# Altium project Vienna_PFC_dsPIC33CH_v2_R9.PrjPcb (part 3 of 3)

## Sheet Vienna_PFC_EMIFilter.SchDoc
size D; DocumentNumber: 2; SheetNumber: 2; SheetTotal: 11
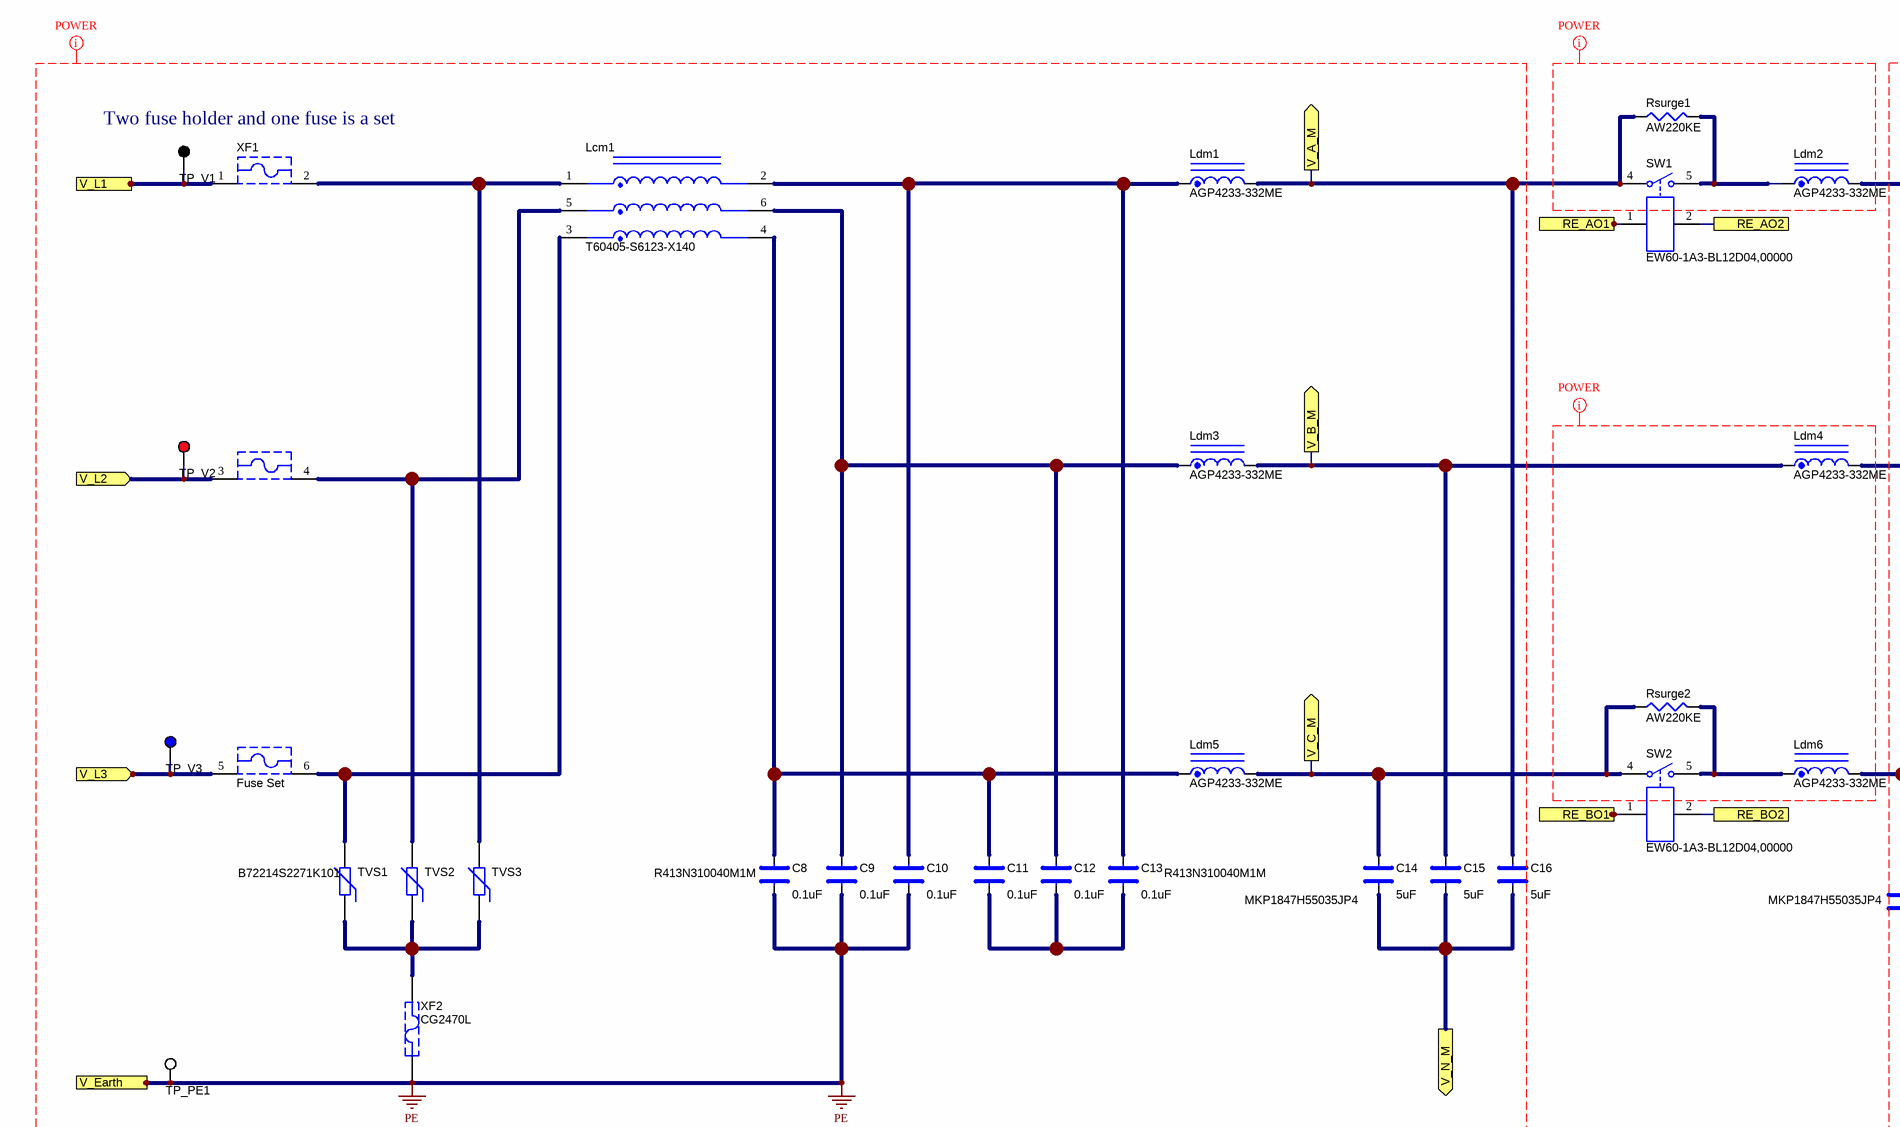
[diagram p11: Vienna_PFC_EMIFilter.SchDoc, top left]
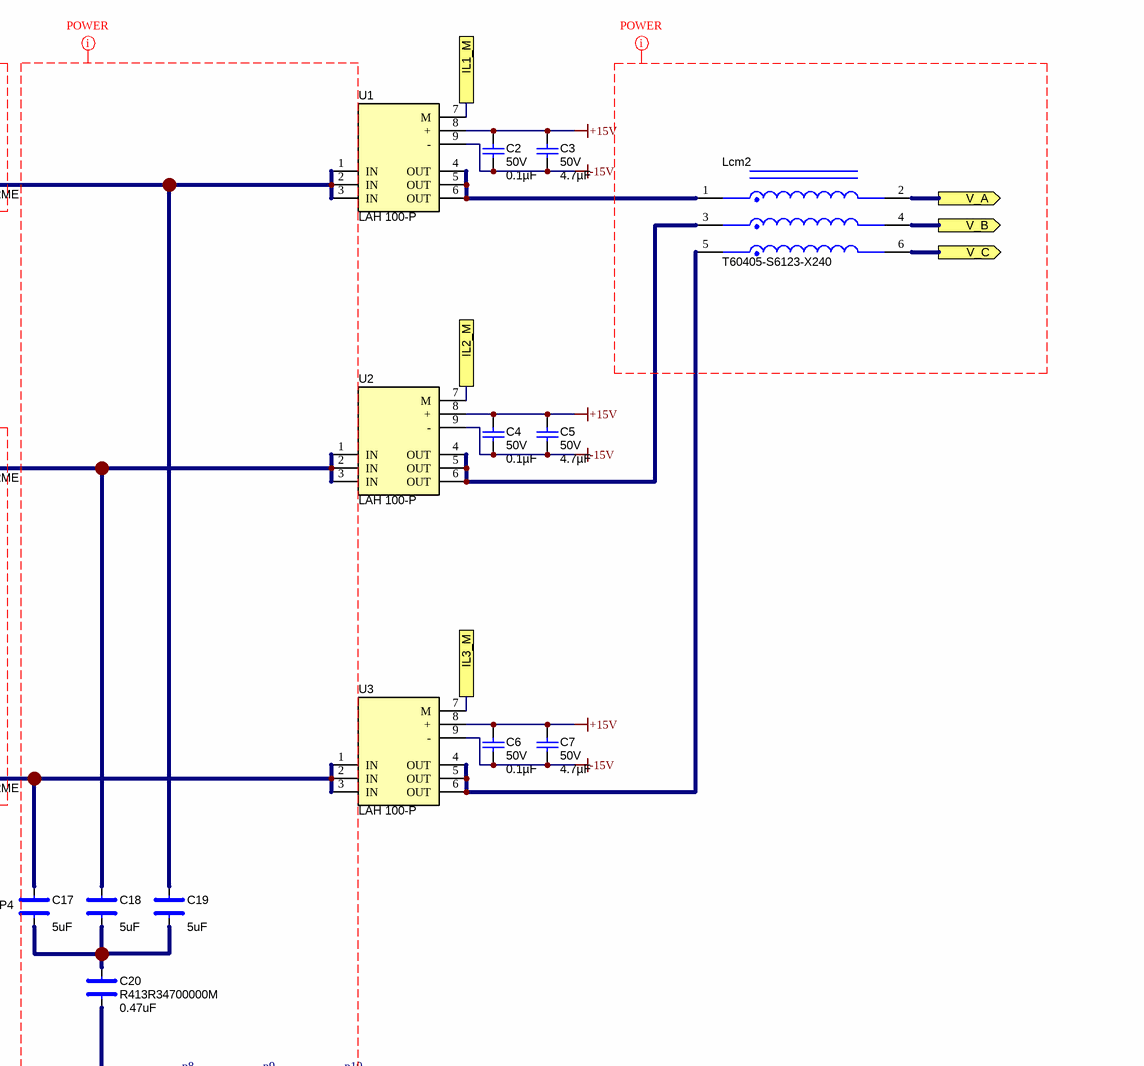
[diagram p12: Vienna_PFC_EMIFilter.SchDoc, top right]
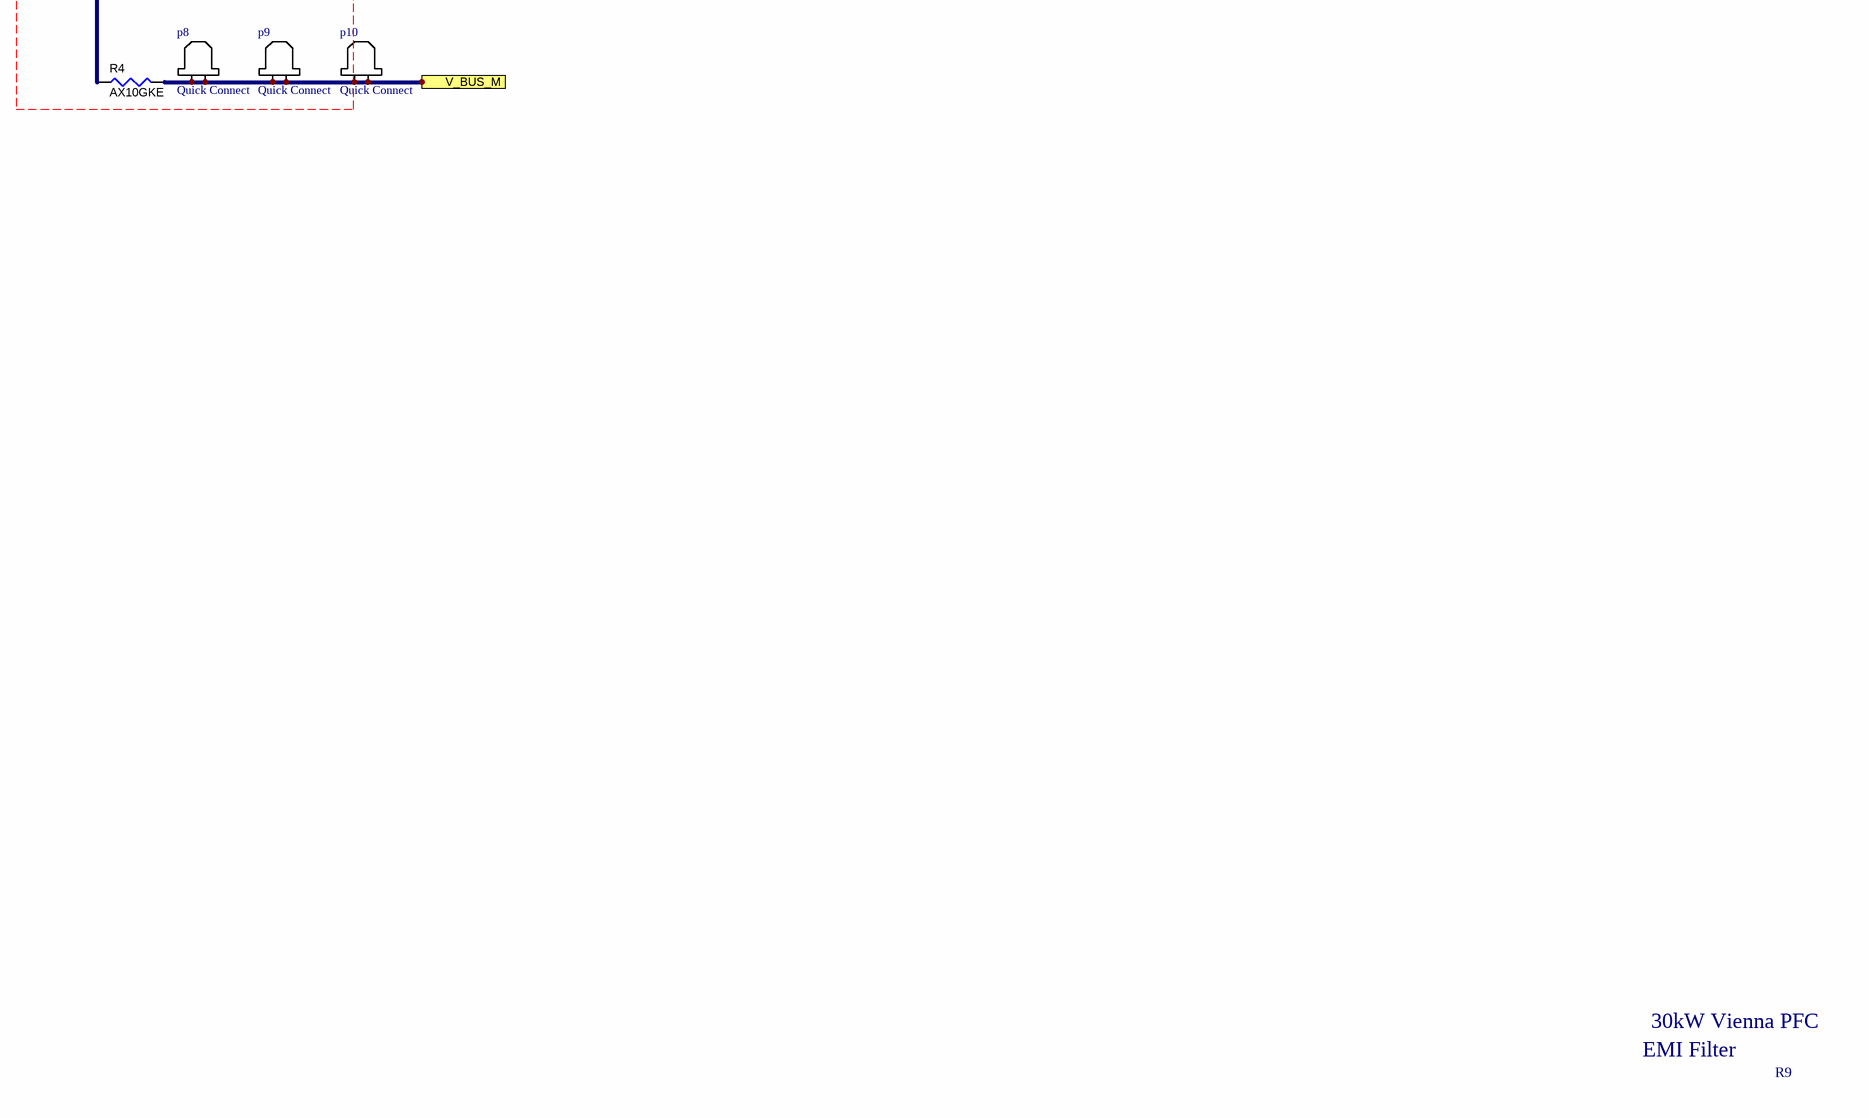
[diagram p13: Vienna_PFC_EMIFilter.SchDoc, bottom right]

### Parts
(Parts that share a designator on the sheet are numbered #1, #2 ... from top to bottom, then left to right.)
?#9  (no value)  (graphical)
C2  VDC_V: 50V  ValueDisplayed: 0.1µF  [0805_HV]  (hidden comment: C0805C104J5RACTU)
C3  VDC_V: 50V  ValueDisplayed: 4.7µF  [0805_HV]  (hidden comment: C2012X5R1H475K125AB)
C4  VDC_V: 50V  ValueDisplayed: 0.1µF  [0805_HV]  (hidden comment: C0805C104J5RACTU)
C5  VDC_V: 50V  ValueDisplayed: 4.7µF  [0805_HV]  (hidden comment: C2012X5R1H475K125AB)
C6  VDC_V: 50V  ValueDisplayed: 0.1µF  [0805_HV]  (hidden comment: C0805C104J5RACTU)
C7  VDC_V: 50V  ValueDisplayed: 4.7µF  [0805_HV]  (hidden comment: C2012X5R1H475K125AB)
C8  R413N310040M1M  value 0.1uF  [R413N310040M1M]
C9  value 0.1uF  [R413N310040M1M]  (hidden comment: R413N310040M1M)
C10  value 0.1uF  [R413N310040M1M]  (hidden comment: R413N310040M1M)
C11  value 0.1uF  [R413N310040M1M]  (hidden comment: R413N310040M1M)
C12  value 0.1uF  [R413N310040M1M]  (hidden comment: R413N310040M1M)
C13  R413N310040M1M  value 0.1uF  [R413N310040M1M]
C14  MKP1847H55035JP4  value 5uF  [MKP1847H55035JP4]
C15  value 5uF  [MKP1847H55035JP4]  (hidden comment: MKP1847H55035JP4)
C16  value 5uF  [MKP1847H55035JP4]  (hidden comment: MKP1847H55035JP4)
C17  MKP1847H55035JP4  value 5uF  [MKP1847H55035JP4]
C18  value 5uF  [MKP1847H55035JP4]  (hidden comment: MKP1847H55035JP4)
C19  value 5uF  [MKP1847H55035JP4]  (hidden comment: MKP1847H55035JP4)
C20  R413R34700000M  value 0.47uF  [R413R34700000M]
Lcm1  T60405-S6123-X140  [T60405-S6123-X140]
Lcm2  T60405-S6123-X240  [T60405-S6123-X240]
Ldm1  AGP4233-332ME  [AGP4233-332ME]
Ldm2  AGP4233-332ME  [AGP4233-332ME]
Ldm3  AGP4233-332ME  [AGP4233-332ME]
Ldm4  AGP4233-332ME  [AGP4233-332ME]
Ldm5  AGP4233-332ME  [AGP4233-332ME]
Ldm6  AGP4233-332ME  [AGP4233-332ME]
p8  Quick Connect  [Quick Connect-4.75mm]
p9  Quick Connect  [Quick Connect-4.75mm]
p10  Quick Connect  [Quick Connect-4.75mm]
R4  AX10GKE  [AX10GKE]
Rsurge1  AW220KE  [AW220KE]
Rsurge2  AW220KE  [AW220KE]
SW1  EW60-1A3-BL12D04,00000  [EW60-1A3-BL12D04,00000]
SW2  EW60-1A3-BL12D04,00000  [EW60-1A3-BL12D04,00000]
TP_PE1  5012  [Keystone5012]  (value not drawn)
TP_V1  5011  [Keystone5011]  (value not drawn)
TP_V2  5010  [Keystone5010]  (value not drawn)
TP_V3  5127  [Keystone5127]  (value not drawn)
TVS1  B72214S2271K101  [B72214S2271K101]
TVS2  B72214S2271K101  [B72214S2271K101]  (value not drawn)
TVS3  B72214S2271K101  [B72214S2271K101]  (value not drawn)
U1  LAH 100-P  [LAH 100-P]
U2  LAH 100-P  [LAH 100-P]
U3  LAH 100-P  [LAH 100-P]
XF1  Fuse Set  [FuseHolde_Set]
XF2  CG2470L  [CG2470L]

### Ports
IL1_M, IL2_M, IL3_M, RE_AO1, RE_AO2, RE_BO1, RE_BO2, V_A (out), V_A_M (out), V_B (out), V_B_M (out), V_BUS_M, V_C (out), V_C_M (out), V_Earth (in), V_L1 (in), V_L2 (in), V_L3 (in), V_N_M (out)

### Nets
+15V: C2.1 C3.1 C4.1 C5.1 C6.1 C7.1 U1.8(+) U2.8(+) U3.8(+)
-15V: C2.2 C3.2 C4.2 C5.2 C6.2 C7.2 U1.9(-) U2.9(-) U3.9(-)
PE: C8.1 C9.1 C10.1 TP_PE1.1 XF2.2 ; port V_Earth
V_BUS_M: p8.1 p9.1 p10.1 R4.2 ; port V_BUS_M
V_N_Meas: C14.1 C15.1 C16.1 ; port V_N_M
NetC8_2: C8.2 C11.2 Lcm1.4 Ldm5.1
NetC9_2: C9.2 C12.2 Lcm1.6 Ldm3.1
NetC10_2: C10.2 C13.2 Lcm1.2 Ldm1.1
NetC11_1: C11.1 C12.1 C13.1
NetC14_2: C14.2 Ldm5.2 Rsurge2.1 SW2.4 ; port V_C_M
NetC15_2: C15.2 Ldm3.2 Ldm4.1 ; port V_B_M
NetC16_2: C16.2 Ldm1.2 Rsurge1.1 SW1.4 ; port V_A_M
NetC17_1: C17.1 C18.1 C19.1 C20.2
NetC17_2: C17.2 Ldm6.2 U3.1(IN) U3.2(IN) U3.3(IN)
NetC18_2: C18.2 Ldm4.2 U2.1(IN) U2.2(IN) U2.3(IN)
NetC19_2: C19.2 Ldm2.2 U1.1(IN) U1.2(IN) U1.3(IN)
NetC20_1: C20.1 R4.1
NetLboost1_1: Lcm2.2 ; port V_A
NetLboost2_1: Lcm2.4 ; port V_B
NetLboost3_1: Lcm2.6 ; port V_C
NetLcm1_1: Lcm1.1 TVS3.2 XF1.2
NetLcm1_3: Lcm1.3 TVS1.2 XF1.6
NetLcm1_5: Lcm1.5 TVS2.2 XF1.4
NetLcm2_1: Lcm2.1 U1.4(OUT) U1.5(OUT) U1.6(OUT)
NetLcm2_3: Lcm2.3 U2.4(OUT) U2.5(OUT) U2.6(OUT)
NetLcm2_5: Lcm2.5 U3.4(OUT) U3.5(OUT) U3.6(OUT)
NetLdm2_1: Ldm2.1 Rsurge1.2 SW1.5
NetLdm6_1: Ldm6.1 Rsurge2.2 SW2.5
NetP1_1: TP_V1.1 XF1.1 ; port V_L1
NetP3_1: TP_V2.1 XF1.3 ; port V_L2
NetP5_1: TP_V3.1 XF1.5 ; port V_L3
NetR171_2: U1.7(M) ; port IL1_M
NetR174_2: U2.7(M) ; port IL2_M
NetR177_2: U3.7(M) ; port IL3_M
NetR180_2: SW1.1 ; port RE_AO1
NetR181_2: SW1.2 ; port RE_AO2
NetR182_2: SW2.1 ; port RE_BO1
NetR183_2: SW2.2 ; port RE_BO2
NetTVS1_1: TVS1.1 TVS2.1 TVS3.1 XF2.1

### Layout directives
net class POWER: (no net found under the mark), PE

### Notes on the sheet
- (near TP_V1) Two fuse holder and one fuse is a set
- 30kW Vienna PFC
- EMI Filter
- R9

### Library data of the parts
?#9 = Title Block D
C2 C4 C6 = C0805C104J5RACTU: CAP, CERM, 0.1 µF, 50 V, +/- 5%, X7R, 0805; Manufacturer: Kemet; CompType: Capacitor; Tolerance_%: 5; TaMin_C: -55; TaMax_C: 125; Cap_Case: 0805; AEC Category: Q200
C3 C5 C7 = C2012X5R1H475K125AB: CAP, CERM, 4.7 µF, 50 V, +/- 10%, X5R, 0805; Manufacturer: TDK; Polarized: N; CompType: Capacitor; Value: 4.7uF; U/M: EA; Cap_F: 0.0000047; Tolerance_%: 10; Value1: Unknown; TaMin_C: -55; TaMax_C: 85; Cap_Case: 0805; AEC Category: Q200
C8-C13 = R413N310040M1M: CAP FILM 0.1UF 20% 1KVDC RADIAL; Manufacturer: KEMET; CompType: Film Capacitors
C14-C19 = MKP1847H55035JP4: CAP FILM 5UF 5% 700VDC RAD 4LDS; Manufacturer: Vishay BC Components; CompType: Film Capacitors
C20 = R413R34700000M: CAP FILM 0.47UF 20% 1KVDC RADIAL; Manufacturer: KEMET; CompType: Film Capacitors
Lcm1 = T60405-S6123-X140: Common Mode Chokes / Filters 580 uH 40A horiz. 2.5mH; Manufacturer: Vacuumschmelze
Lcm2 = T60405-S6123-X240: Common Mode Chokes / Filters CM Choke 3 phase 40A horiz. 1.5mH; Manufacturer: Vacuumschmelze
Ldm1-Ldm6 = AGP4233-332ME: FIXED IND 3.3UH 34A  TH, Coilcraft; CompType: Fixed Inductors
p8-p10 = Quick Connect: 0.187" (4.75mm) Quick Connect Male Solder
R4 = AX10GKE: RES 1 OHM 3.5W 10% RADIAL; Manufacturer: Ohmite; CompType: Through Hole Resistors
Rsurge1 Rsurge2 = AW220KE: RES 22 OHM 2.5W 10% RADIAL; Manufacturer: Ohmite; CompType: Through Hole Resistors
SW1 SW2 = EW60-1A3-BL12D04: RELAY GEN PURPOSE SPST 60A 12V; Manufacturer: TE Connectivity Potter & Brumfield Relays; CompType: Power Relays
TP_PE1 = 5012: Test Point, Multipurpose, White, TH; Manufacturer: Keystone; CompType: Test Point Loop; ContactFinish: Silver
TP_V1 = 5011: Test Point, Multipurpose, Black, TH; Manufacturer: Keystone; CompType: Test Point Loop; ContactFinish: Silver
TP_V2 = 5010: Test Point, Multipurpose, Red, TH; Manufacturer: Keystone; CompType: Test Point Loop; ContactFinish: Silver
TP_V3 = 5127: Test Point, Multipurpose, Blue, TH; Manufacturer: Keystone; CompType: Test Point Loop; U/M: EA; ContactFinish: Silver
TVS1-TVS3 = B72214S2271K101: VARISTOR 430V 6KA DISC 14MM, EPCOS (TDK); CompType: TVS - Varistors, MOVs
U1-U3 = LAH 100-P: SENSOR CURRENT HALL 100A AC/DC; Manufacturer: LEM USA Inc.; CompType: Current Transducers
XF1 = Fuse Set: 6*5591-52-R, 3*50C14X51AM
XF2 = CG2470L: GDT 470V 20KA THROUGH HOLE,  Littelfuse Inc.; CompType: Gas Discharge Tube Arresters (GDT)

## Sheet Vienna_PFC_Relay.SchDoc
size C; DocumentNumber: 9; SheetNumber: 9; SheetTotal: 11
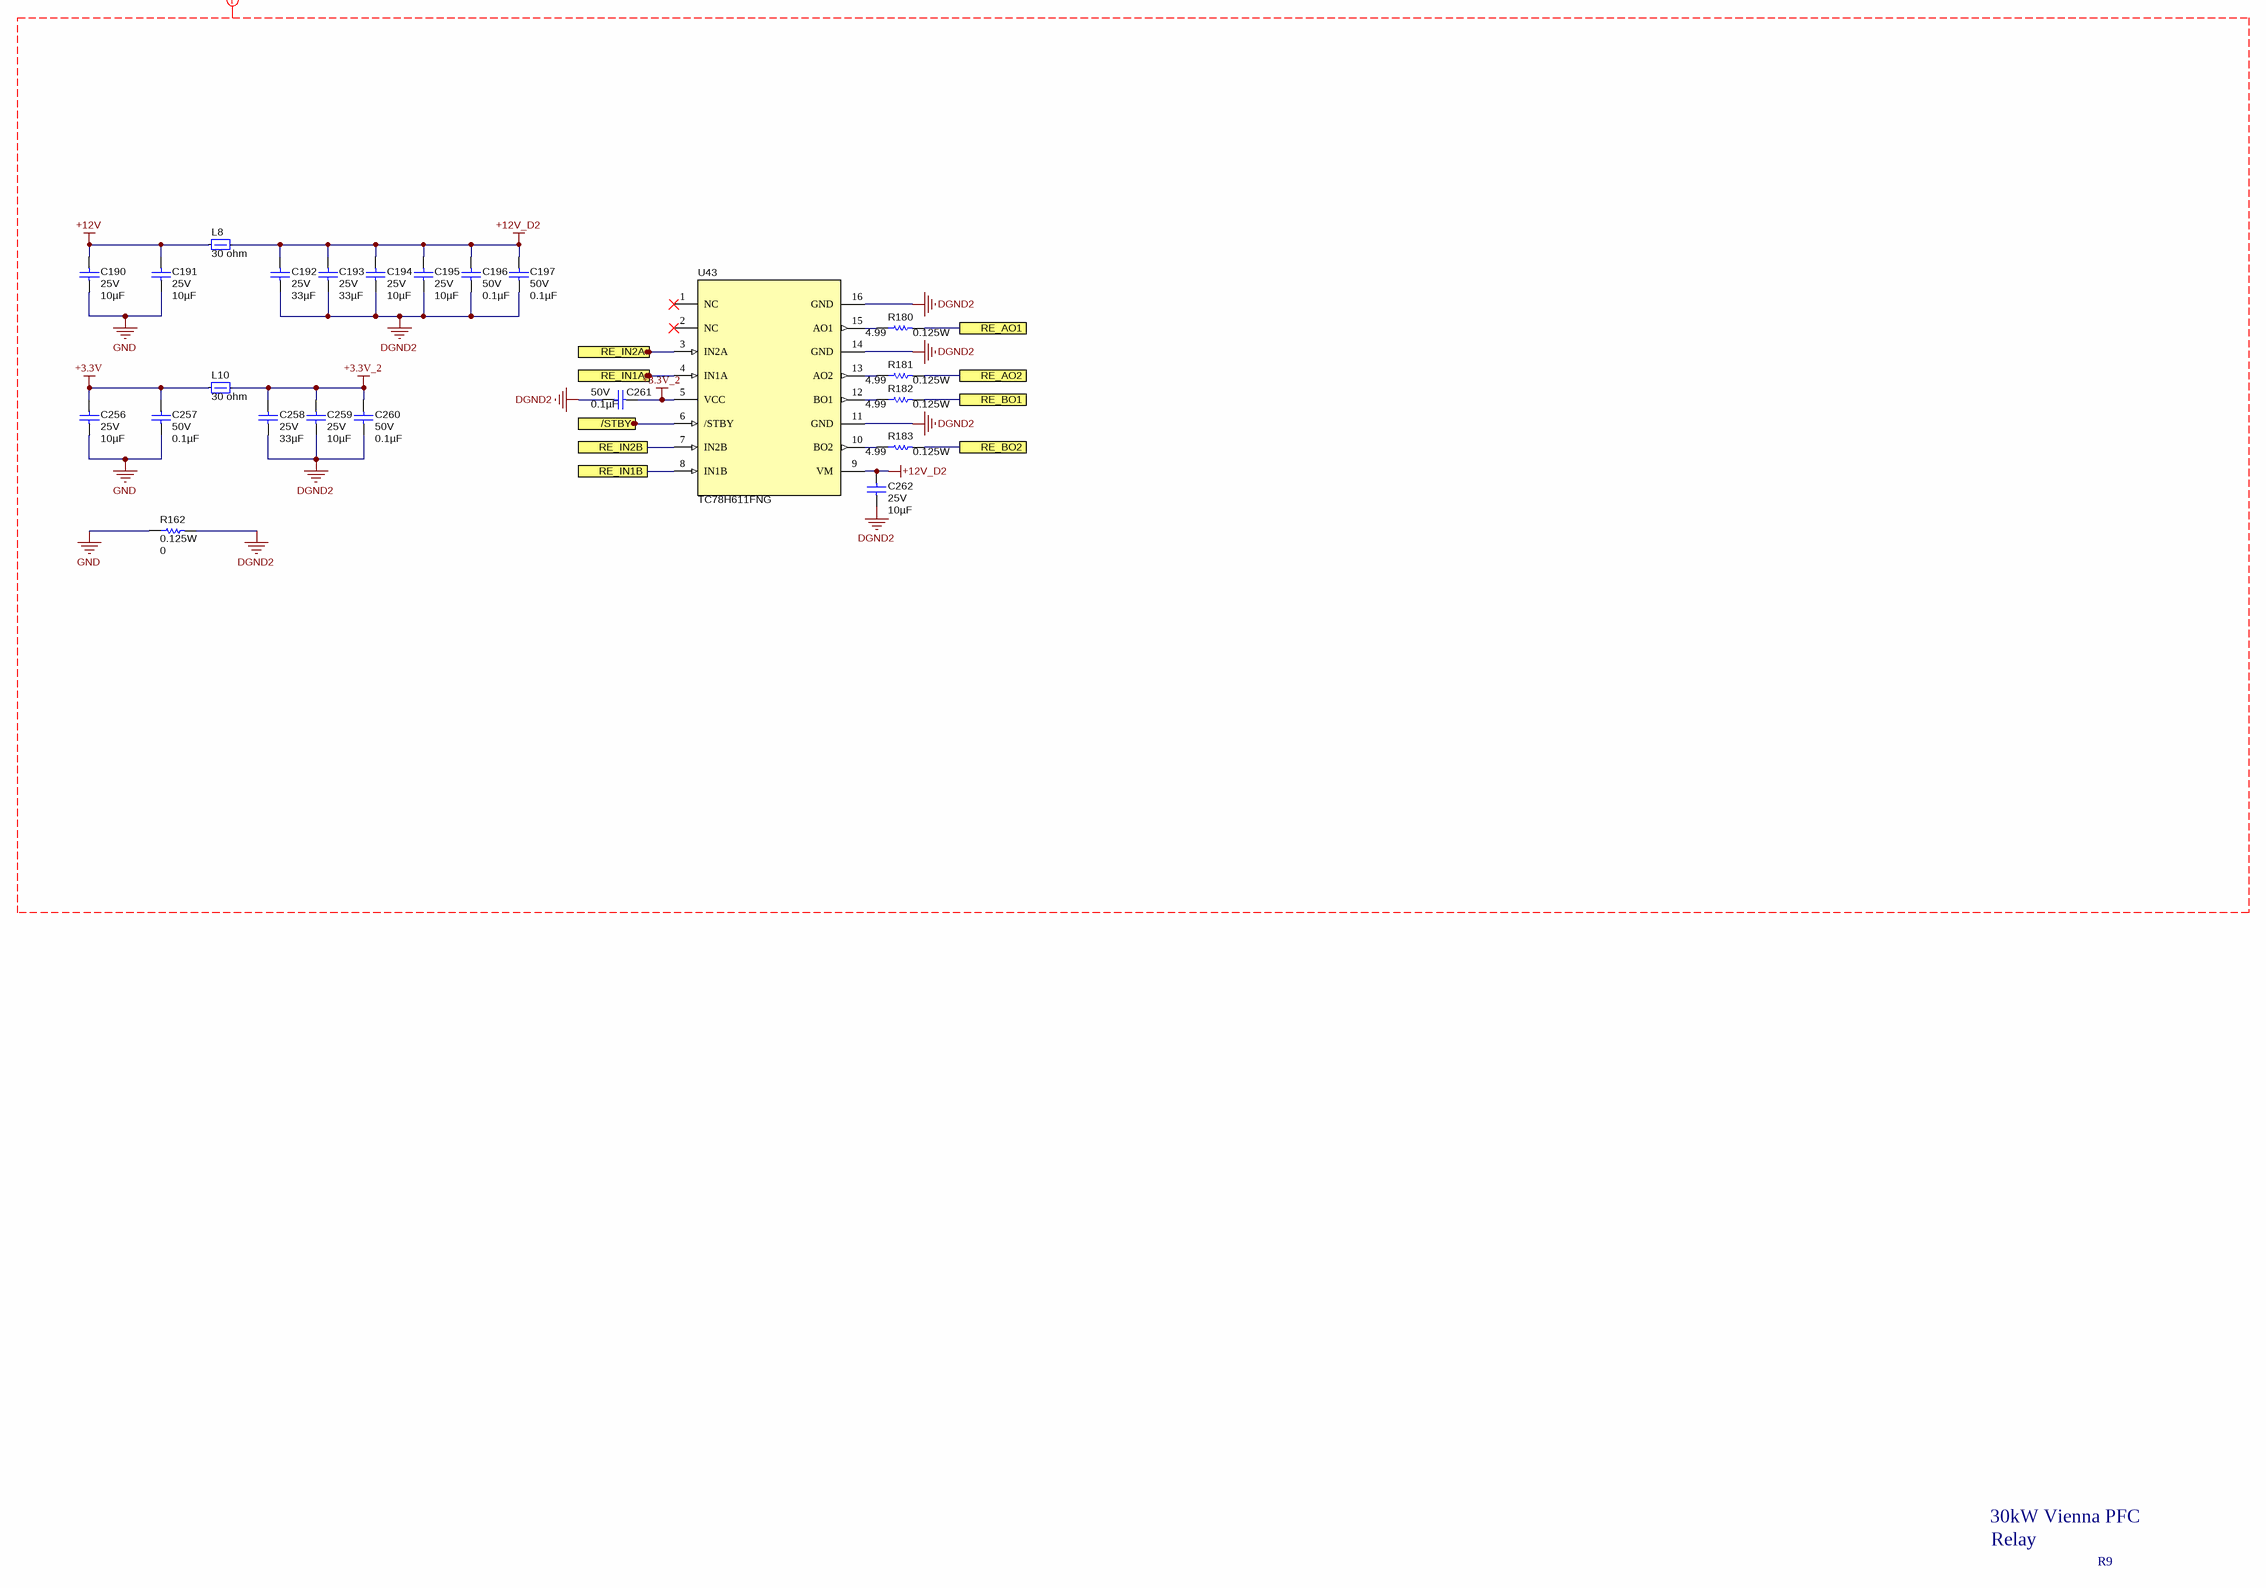
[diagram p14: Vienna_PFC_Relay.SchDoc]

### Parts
(Parts that share a designator on the sheet are numbered #1, #2 ... from top to bottom, then left to right.)
?#10  (no value)  (graphical)
C190  VDC_V: 25V  ValueDisplayed: 10µF  [1206_190]  (hidden comment: C1206C106K3RACAUTO)
C191  VDC_V: 25V  ValueDisplayed: 10µF  [1206_190]  (hidden comment: C1206C106K3RACAUTO)
C192  VDC_V: 25V  ValueDisplayed: 33µF  [1206_190]  (hidden comment: C3216X5R1E336M160AC)
C193  VDC_V: 25V  ValueDisplayed: 33µF  [1206_190]  (hidden comment: C3216X5R1E336M160AC)
C194  VDC_V: 25V  ValueDisplayed: 10µF  [1206_190]  (hidden comment: C1206C106K3RACAUTO)
C195  VDC_V: 25V  ValueDisplayed: 10µF  [1206_190]  (hidden comment: C1206C106K3RACAUTO)
C196  VDC_V: 50V  ValueDisplayed: 0.1µF  [0805_HV]  (hidden comment: C0805C104J5RACTU)
C197  VDC_V: 50V  ValueDisplayed: 0.1µF  [0805_HV]  (hidden comment: C0805C104J5RACTU)
C256  VDC_V: 25V  ValueDisplayed: 10µF  [1206_190]  (hidden comment: C1206C106K3RACAUTO)
C257  VDC_V: 50V  ValueDisplayed: 0.1µF  [0805_HV]  (hidden comment: C0805C104J5RACTU)
C258  VDC_V: 25V  ValueDisplayed: 33µF  [1206_190]  (hidden comment: C3216X5R1E336M160AC)
C259  VDC_V: 25V  ValueDisplayed: 10µF  [1206_190]  (hidden comment: C1206C106K3RACAUTO)
C260  VDC_V: 50V  ValueDisplayed: 0.1µF  [0805_HV]  (hidden comment: C0805C104J5RACTU)
C261  VDC_V: 50V  ValueDisplayed: 0.1µF  [0805_HV]  (hidden comment: C0805C104J5RACTU)
C262  VDC_V: 25V  ValueDisplayed: 10µF  [1206_190]  (hidden comment: C1206C106K3RACAUTO)
L8  value 30 ohm  [0805_HV]  (hidden comment: MPZ2012S300AT000)
L10  value 30 ohm  [0805_HV]  (hidden comment: MPZ2012S300AT000)
R162  Value2: 0.125W  ValueDisplayed: 0  [0805_HV]  (hidden comment: CRCW08050000Z0EA)
R180  Value2: 0.125W  ValueDisplayed: 4.99  [0805_HV]  (hidden comment: CRCW08054R99FKEAC)
R181  Value2: 0.125W  ValueDisplayed: 4.99  [0805_HV]  (hidden comment: CRCW08054R99FKEAC)
R182  Value2: 0.125W  ValueDisplayed: 4.99  [0805_HV]  (hidden comment: CRCW08054R99FKEAC)
R183  Value2: 0.125W  ValueDisplayed: 4.99  [0805_HV]  (hidden comment: CRCW08054R99FKEAC)
U43  TC78H611FNG  [TSSOP16_small pins]

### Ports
/STBY, RE_AO1, RE_AO2, RE_BO1, RE_BO2, RE_IN1A, RE_IN1B, RE_IN2A, RE_IN2B

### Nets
+3.3V: C256.1 C257.1 L10.1
+3.3V_2: C258.1 C259.1 C260.1 C261.1 L10.2 U43.5(VCC)
+12V: C190.1 C191.1 L8.1
+12V_D2: C192.1 C193.1 C194.1 C195.1 C196.1 C197.1 C262.1 L8.2 U43.9(VM)
DGND2: C192.2 C193.2 C194.2 C195.2 C196.2 C197.2 C258.2 C259.2 C260.2 C261.2 C262.2 R162.2 U43.11(GND) U43.14(GND) U43.16(GND)
GND: C190.2 C191.2 C256.2 C257.2 R162.1
NetJ5_13: U43.8(IN1B) ; port RE_IN1B
NetJ5_15: U43.7(IN2B) ; port RE_IN2B
NetJ5_31: U43.6(/STBY) ; port /STBY
NetJ5_33: U43.4(IN1A) ; port RE_IN1A
NetJ5_35: U43.3(IN2A) ; port RE_IN2A
NetR180_1: R180.1 U43.15(AO1)
NetR180_2: R180.2 ; port RE_AO1
NetR181_1: R181.1 U43.13(AO2)
NetR181_2: R181.2 ; port RE_AO2
NetR182_1: R182.1 U43.12(BO1)
NetR182_2: R182.2 ; port RE_BO1
NetR183_1: R183.1 U43.10(BO2)
NetR183_2: R183.2 ; port RE_BO2

Not connected (* = marked no-connect by the designer): U43 1(NC)* 2(NC)*

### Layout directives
net class Relay: +3.3V, +3.3V_2, +12V, +12V_D2, DGND2, GND

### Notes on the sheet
- 30kW Vienna PFC
- Relay
- R9

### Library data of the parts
?#10 = Title Block C
C190 C191 C194 C195 C256 C259 C262 = C1206C106K3RACAUTO: CAP, CERM, 10 µF, 25 V, +/- 10%, X7R, 1206_190; Manufacturer: Kemet; Polarized: N; CompType: Capacitor; Value: 10uF; U/M: EA; Cap_F: 0.00001; Tolerance_%: 10; Value1: Unknown; TaMin_C: -55; TaMax_C: 125; Cap_Case: 1206; AEC Category: Q200
C192 C193 C258 = C3216X5R1E336M160AC: CAP, CERM, 33 µF, 25 V, +/- 20%, X5R, 1206; Manufacturer: TDK; Polarized: N; CompType: Capacitor; Value: 33uF; U/M: EA; Tolerance_%: 20; Value1: Unknown; TaMin_C: -55; TaMax_C: 85; Cap_Case: 1206; AEC Category: Q200
C196 C197 C257 C260 C261 = C0805C104J5RACTU: as C2 on sheet Vienna_PFC_EMIFilter
L8 L10 = MPZ2012S300AT000: Ferrite Bead, 30 ohm @ 100 MHz, 6 A, 0805; Manufacturer: TDK; Imax_A: 6; DCR_ohm: 0.01; Value1: 0.01 ohm; Value2: 6A; ZTyp@100MHz_Ohm: 30
R162 = CRCW08050000Z0EA: RES, 0, 5%, 0.125 W, 0805; Manufacturer: Vishay-Dale; CompType: Resistor; Value: 0; Tolerance_%: 5; Power_W: 0.125; VDC_V: 150; TempCo: 200 ppm/C; EIA_Code: E24; U/M: EA; AEC Category: Q200
R180-R183 = CRCW08054R99FKEAC: RES, 4.99 1%, 0.125 W, 0805; Manufacturer: Vishay-Dale; CompType: Resistor; Value: 4.99; Value_Code: 4R99; Tolerance_%: 1; Power_W: 0.125; VDC_V: 150; TempCo: 100 ppm/C; SizeArea_mm2: 2.5; SizeX_mm: 2; SizeY_mm: 1.25; SizeZ_mm: 1.45; EIA_Code: E24; U/M: EA; AEC Category: Q200
U43 = TC78H611FNG: BRUSHED MOTOR DRIVER IC 2-CHANNE; Manufacturer: Toshiba Semiconductor and Storage

## Sheet Vienna_PFC_Controller.SchDoc
size C; DocumentNumber: 10; SheetNumber: 10; SheetTotal: 11
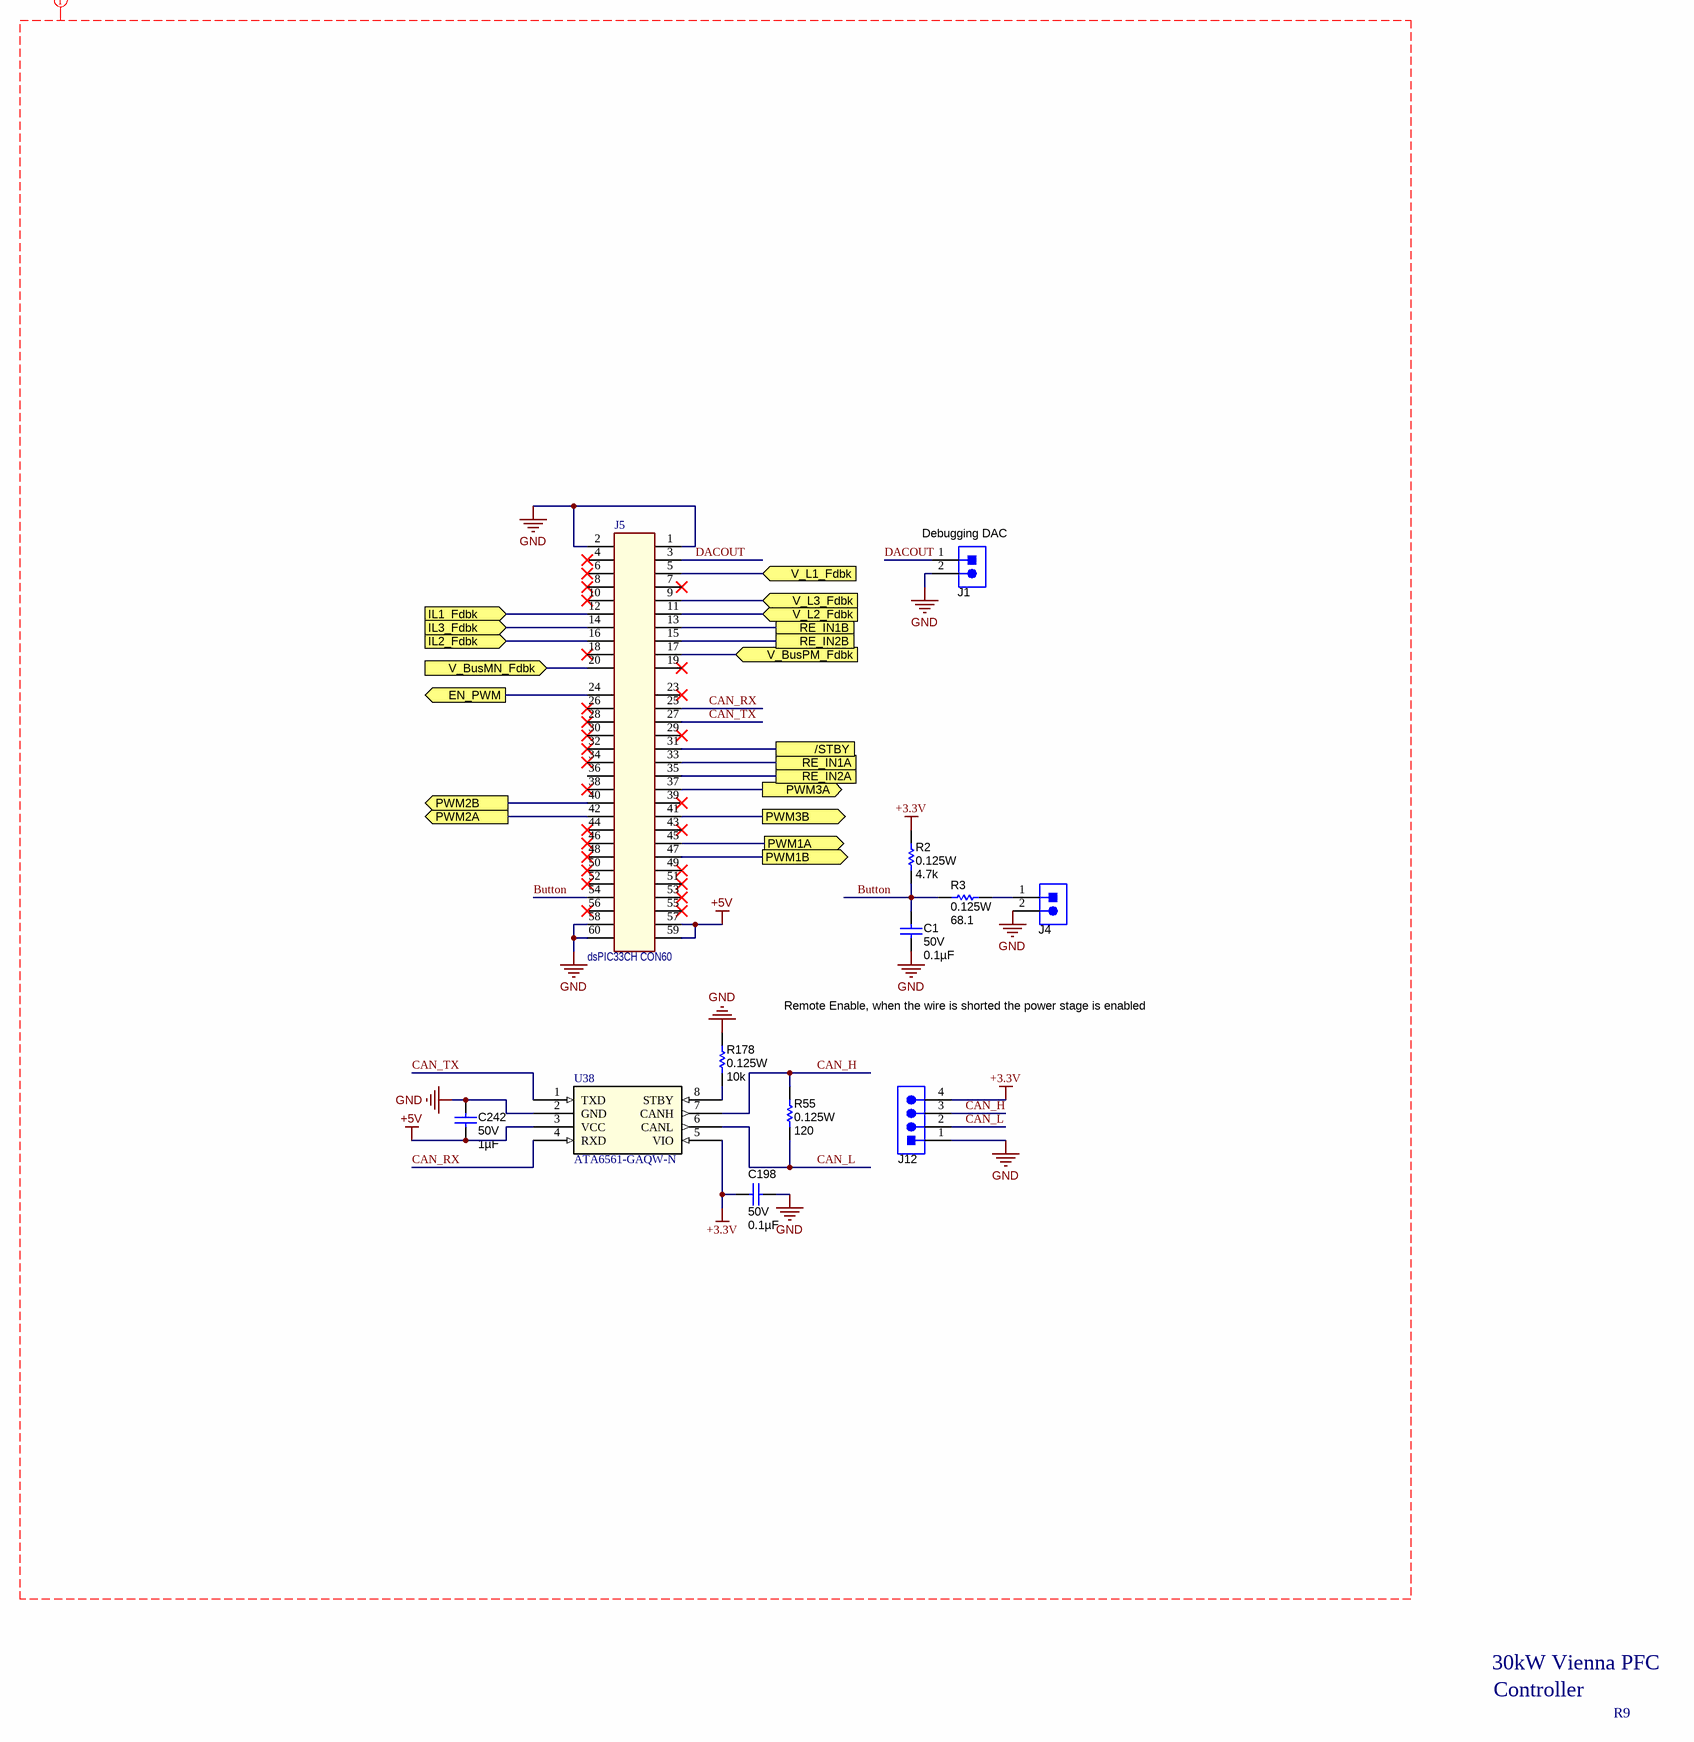
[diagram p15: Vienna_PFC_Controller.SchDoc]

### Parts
(Parts that share a designator on the sheet are numbered #1, #2 ... from top to bottom, then left to right.)
?#11  (no value)  (graphical)
C1  VDC_V: 50V  ValueDisplayed: 0.1µF  [0805_HV]  (hidden comment: C0805C104J5RACTU)
C198  VDC_V: 50V  ValueDisplayed: 0.1µF  [0805_HV]  (hidden comment: C0805C104J5RACTU)
C242  VDC_V: 50V  ValueDisplayed: 1µF  [0805_HV]  (hidden comment: C0805C105K5RACTU)
J1  HTSW-102-07-G-S  [Samtec_HTSW-102-07-G-S]  (value not drawn)
J4  HTSW-102-07-G-S  [Samtec_HTSW-102-07-G-S]  (value not drawn)
J5  value dsPIC33CH CON60  [HDR_F_1.27_2X30_V_SMD_MECF-30-01-L-DV-WT]  (hidden comment: CON EDGE-CARD PCB SAM MECF-30-01-L-DV-WT)  (no BOM)
J12  Fan Connector  [Fan Connector]  (value not drawn)
R2  Value2: 0.125W  ValueDisplayed: 4.7k  [0805_HV]  (hidden comment: CRCW080510K0FKEA)
R3  Value2: 0.125W  ValueDisplayed: 68.1  [0805_HV]  (hidden comment: ERJ-6ENF68R1V)
R55  Value2: 0.125W  ValueDisplayed: 120  [0805_HV]  (hidden comment: CRCW0805120RFKTA)
R178  Value2: 0.125W  ValueDisplayed: 10k  [0805_HV]  (hidden comment: CRCW080510K0FKEA)
U38  ATA6561-GAQW-N  [SOIC8]

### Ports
/STBY, EN_PWM (out), IL1_Fdbk (in), IL2_Fdbk (in), IL3_Fdbk (in), PWM1A (out), PWM1B (out), PWM2A (out), PWM2B (out), PWM3A (out), PWM3B (out), RE_IN1A, RE_IN1B, RE_IN2A, RE_IN2B, V_BusMN_Fdbk (in), V_BusPM_Fdbk (in), V_L1_Fdbk (in), V_L2_Fdbk (in), V_L3_Fdbk (in)

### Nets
+3.3V: C198.1 J12.4(CONTROL_BLUE) R2.2 U38.5(VIO)
+5V: C242.2 J5.57 J5.59 U38.3(VCC)
GND: C1.2 C198.2 C242.1 J1.2 J4.2 J5.1 J5.2 J5.58 J5.60 J12.1(GND_BLACK) R178.2 U38.2(GND)
Button: C1.1 J5.54 R2.1 R3.2
CAN_H: J12.3(SENSE_YELLOW) R55.2 U38.7(CANH)
CAN_L: J12.2(+VCC_RED) R55.1 U38.6(CANL)
CAN_RX: J5.25 U38.4(RXD)
CAN_TX: J5.27 U38.1(TXD)
DACOUT: J1.1 J5.3
EN_PWM: J5.24 ; port EN_PWM
NetC110_1: J5.12 ; port IL1_Fdbk
NetC112_1: J5.16 ; port IL2_Fdbk
NetC114_1: J5.14 ; port IL3_Fdbk
NetC122_2: J5.5 ; port V_L1_Fdbk
NetC139_2: J5.11 ; port V_L2_Fdbk
NetC149_2: J5.9 ; port V_L3_Fdbk
NetC159_2: J5.17 ; port V_BusPM_Fdbk
NetC168_2: J5.20 ; port V_BusMN_Fdbk
NetJ4_1: J4.1 R3.1
NetJ5_13: J5.13 ; port RE_IN1B
NetJ5_15: J5.15 ; port RE_IN2B
NetJ5_31: J5.31 ; port /STBY
NetJ5_33: J5.33 ; port RE_IN1A
NetJ5_35: J5.35 ; port RE_IN2A
NetJ5_37: J5.37 ; port PWM3A
NetJ5_40: J5.40 ; port PWM2B
NetJ5_41: J5.41 ; port PWM3B
NetJ5_42: J5.42 ; port PWM2A
NetJ5_45: J5.45 ; port PWM1A
NetJ5_47: J5.47 ; port PWM1B
NetR178_1: R178.1 U38.8(STBY)

Not connected (* = marked no-connect by the designer): J5 4* 6* 7* 8* 10* 18* 19* 23* 26* 28* 29* 30* 32* 34* 36 38* 39* 43* 44* 46* 48* 49* 50* 51* 52* 53* 55* 56*

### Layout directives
net class Controller: +3.3V, +5V, Button, CAN_H, CAN_L, CAN_RX, CAN_TX, DACOUT, GND

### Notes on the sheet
- (near J1) Debugging DAC
- Remote Enable, when the wire is shorted the power stage is enabled
- 30kW Vienna PFC
- Controller
- R9

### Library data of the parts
?#11 = Title Block C
C1 C198 = C0805C104J5RACTU: as C2 on sheet Vienna_PFC_EMIFilter
C242 = C0805C105K5RACTU: CAP, CERM, 1 µF, 50 V, +/- 5%, X7R, 0805; Manufacturer: Kemet; CompType: Capacitor; Tolerance_%: 10; TaMin_C: -55; TaMax_C: 125; Cap_Case: 0805; AEC Category: Q200
J1 J4 = HTSW-102-07-G-S: Header, 100mil, 2x1, Gold, TH; Manufacturer: Samtec; SymbolCreator: a0412235
J5 = CON EDGE-CARD PCB SAM MECF-30-01-L-DV-WT: Get it already; MCHP-ID: CON1706; Dev Tools Status: Design; Owner: Tim Moffat; Populated: YES
J12 = Fan Connector: 4 Positions Header Connector 0.100" (2.54mm) Through Hole Tin; Manufacturer: TE Connectivity AMP Connectors
R2 = CRCW08054K70FKEA: RES, 4.7K, 1%, 0.125 W, 0805; Manufacturer: Vishay-Dale; CompType: Resistor; Tolerance_%: 1; Power_W: 0.125; VDC_V: 150; TempCo: 100 ppm/C; EIA_Code: E96; U/M: EA; AEC Category: Q200
R3 = CRCW08054K70FKEA: RES SMD 68.1 OHM 1% 1/8W 0805; Manufacturer: Vishay-Dale; CompType: Resistor; Value: 68.1; Tolerance_%: 1; Power_W: 0.125; VDC_V: 150; TempCo: 100 ppm/C; EIA_Code: E96; U/M: EA; AEC Category: Q200
R55 = CRCW0805120RFKTA: RES, 120, 1%, 0.125 W, 0805; Manufacturer: Vishay-Dale; CompType: Resistor; Value: 120; Value_Code: 120R; Tolerance_%: 1; Power_W: 0.125; VDC_V: 150; TempCo: 100 ppm/C; EIA_Code: E96; U/M: EA; AEC Category: Q200
R178 = CRCW080510K0FKEA: RES, 10K, 1%, 0.125 W, 0805; Manufacturer: Vishay-Dale; CompType: Resistor; Tolerance_%: 1; Power_W: 0.125; VDC_V: 150; TempCo: 100 ppm/C; EIA_Code: E96; U/M: EA; AEC Category: Q200
U38 = ATA6561-GAQW-N: CAN Interface IC Industrial Grade CAN TRX with VIO PIN (SO8); Manufacturer: Microchip Technology / Atmel; GENERIC_PART_NUMBER: SN65HVD234; INDUSTRY_STD_PKG_TYPE: SOIC; PIN_COUNT: 8; PACKAGE_DESIGNATOR: D; Vendor: Mouser

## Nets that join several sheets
+3.3V: Vienna_PFC_InputVoltageSensor (15 pins), Vienna_PFC_GateDriver (C34.1 C35.1 L1.1), Vienna_PFC_OutputVoltageSensor (10 pins), Vienna_PFC_InductorCurrentSensor (6 pins), Vienna_PFC_PowerSupply (C216.1 C217.1 R166.2 U34.3), Vienna_PFC_Relay (C256.1 C257.1 L10.1), Vienna_PFC_Controller (C198.1 J12.4 R2.2 U38.5)
+5V: Vienna_PFC_InputVoltageSensor (C135.1 L3.1 L4.1), Vienna_PFC_OutputVoltageSensor (C171.1 L6.1), Vienna_PFC_InductorCurrentSensor (C252.1 U42.1), Vienna_PFC_PowerSupply (6 pins), Vienna_PFC_Controller (C242.2 J5.57 J5.59 U38.3)
+12V: Vienna_PFC_GateDriver (C51.1 C52.1 L2.1), Vienna_PFC_PowerSupply (11 pins), Vienna_PFC_Relay (C190.1 C191.1 L8.1)
+15V: Vienna_PFC_InductorCurrentSensor (6 pins), Vienna_PFC_PowerSupply (5 pins), Vienna_PFC_EMIFilter (9 pins)
-15V: Vienna_PFC_InductorCurrentSensor (6 pins), Vienna_PFC_PowerSupply (5 pins), Vienna_PFC_EMIFilter (9 pins)
GND: Vienna_PFC_InputVoltageSensor (36 pins), Vienna_PFC_GateDriver (5 pins), Vienna_PFC_OutputVoltageSensor (20 pins), Vienna_PFC_InductorCurrentSensor (30 pins), Vienna_PFC_PowerSupply (32 pins), Vienna_PFC_Relay (5 pins), Vienna_PFC_Controller (12 pins)
GND1: Vienna_PFC_PowerStage (Q7.3 Q8.3 Q9.3 Q10.3), Vienna_PFC_GateDriver (21 pins)
GND3: Vienna_PFC_PowerStage (Q11.3 Q12.3 Q13.3 Q14.3), Vienna_PFC_GateDriver (21 pins)
GND5: Vienna_PFC_PowerStage (Q15.3 Q16.3 Q17.3 Q18.3), Vienna_PFC_GateDriver (21 pins)
PE: Vienna_PFC_Overall (P7.1), Vienna_PFC_EMIFilter (5 pins)
EN_PWM: Vienna_PFC_GateDriver (7 pins), Vienna_PFC_Controller (J5.24)
NetC14_2: Vienna_PFC_InputVoltageSensor (R96.2), Vienna_PFC_EMIFilter (C14.2 Ldm5.2 Rsurge2.1 SW2.4)
NetC15_2: Vienna_PFC_InputVoltageSensor (R84.2), Vienna_PFC_EMIFilter (C15.2 Ldm3.2 Ldm4.1)
NetC16_2: Vienna_PFC_InputVoltageSensor (R72.2), Vienna_PFC_EMIFilter (C16.2 Ldm1.2 Rsurge1.1 SW1.4)
NetC110_1: Vienna_PFC_InductorCurrentSensor (C110.1 R56.2 TP_IL1.1), Vienna_PFC_Controller (J5.12)
NetC112_1: Vienna_PFC_InductorCurrentSensor (C112.1 R62.2 TP_IL2.1), Vienna_PFC_Controller (J5.16)
NetC114_1: Vienna_PFC_InductorCurrentSensor (C114.1 R68.2 TP_IL3.1), Vienna_PFC_Controller (J5.14)
NetC122_2: Vienna_PFC_InputVoltageSensor (C122.2 R79.2 TP_VL1.1), Vienna_PFC_Controller (J5.5)
NetC139_2: Vienna_PFC_InputVoltageSensor (C139.2 R91.2 TP_VL2.1), Vienna_PFC_Controller (J5.11)
NetC149_2: Vienna_PFC_InputVoltageSensor (C149.2 R103.2 TP_VL3.1), Vienna_PFC_Controller (J5.9)
NetC159_2: Vienna_PFC_OutputVoltageSensor (C159.2 R115.2 TP_VBUSPM_Fdbk1.1), Vienna_PFC_Controller (J5.17)
NetC168_2: Vienna_PFC_OutputVoltageSensor (C168.2 R127.2 TP_VBUSMN_Fdbk1.1), Vienna_PFC_Controller (J5.20)
NetJ5_13: Vienna_PFC_Relay (U43.8), Vienna_PFC_Controller (J5.13)
NetJ5_15: Vienna_PFC_Relay (U43.7), Vienna_PFC_Controller (J5.15)
NetJ5_31: Vienna_PFC_Relay (U43.6), Vienna_PFC_Controller (J5.31)
NetJ5_33: Vienna_PFC_Relay (U43.4), Vienna_PFC_Controller (J5.33)
NetJ5_35: Vienna_PFC_Relay (U43.3), Vienna_PFC_Controller (J5.35)
NetJ5_37: Vienna_PFC_GateDriver (R9.1 R16.2 TP_G1.1), Vienna_PFC_Controller (J5.37)
NetJ5_40: Vienna_PFC_GateDriver (R24.1 R31.2 TP_G4.1), Vienna_PFC_Controller (J5.40)
NetJ5_41: Vienna_PFC_GateDriver (R7.1 R14.2 TP_G2.1), Vienna_PFC_Controller (J5.41)
NetJ5_42: Vienna_PFC_GateDriver (R26.1 R33.2 TP_G3.1), Vienna_PFC_Controller (J5.42)
NetJ5_45: Vienna_PFC_GateDriver (R42.1 R49.2 TP_G5.1), Vienna_PFC_Controller (J5.45)
NetJ5_47: Vienna_PFC_GateDriver (R40.1 R47.2 TP_G6.1), Vienna_PFC_Controller (J5.47)
NetLboost1_1: Vienna_PFC_PowerStage (Lboost1.1), Vienna_PFC_EMIFilter (Lcm2.2)
NetLboost2_1: Vienna_PFC_PowerStage (Lboost2.1), Vienna_PFC_EMIFilter (Lcm2.4)
NetLboost3_1: Vienna_PFC_PowerStage (Lboost3.1), Vienna_PFC_EMIFilter (Lcm2.6)
NetP1_1: Vienna_PFC_Overall (P1.1), Vienna_PFC_EMIFilter (TP_V1.1 XF1.1)
NetP3_1: Vienna_PFC_Overall (P3.1), Vienna_PFC_EMIFilter (TP_V2.1 XF1.3)
NetP5_1: Vienna_PFC_Overall (P5.1), Vienna_PFC_EMIFilter (TP_V3.1 XF1.5)
NetR11_2: Vienna_PFC_PowerStage (R139.2 R141.2), Vienna_PFC_GateDriver (R11.2 R13.2 TP_GS2.1)
NetR12_2: Vienna_PFC_PowerStage (R138.1 R140.1), Vienna_PFC_GateDriver (R12.2 R15.2 TP_GS1.1)
NetR28_2: Vienna_PFC_PowerStage (R143.2 R145.2), Vienna_PFC_GateDriver (R28.2 R30.2 TP_GS4.1)
NetR29_2: Vienna_PFC_PowerStage (R142.1 R144.1), Vienna_PFC_GateDriver (R29.2 R32.2 TP_GS3.1)
NetR44_2: Vienna_PFC_PowerStage (R151.2 R155.2), Vienna_PFC_GateDriver (R44.2 R46.2 TP_GS6.1)
NetR45_2: Vienna_PFC_PowerStage (R150.1 R154.1), Vienna_PFC_GateDriver (R45.2 R48.2 TP_GS5.1)
NetR171_2: Vienna_PFC_InductorCurrentSensor (R171.2 TP_IIn1.1 U39.3), Vienna_PFC_EMIFilter (U1.7)
NetR174_2: Vienna_PFC_InductorCurrentSensor (R174.2 TP_IIn2.1 U40.3), Vienna_PFC_EMIFilter (U2.7)
NetR177_2: Vienna_PFC_InductorCurrentSensor (R177.2 TP_IIn3.1 U41.3), Vienna_PFC_EMIFilter (U3.7)
NetR180_2: Vienna_PFC_EMIFilter (SW1.1), Vienna_PFC_Relay (R180.2)
NetR181_2: Vienna_PFC_EMIFilter (SW1.2), Vienna_PFC_Relay (R181.2)
NetR182_2: Vienna_PFC_EMIFilter (SW2.1), Vienna_PFC_Relay (R182.2)
NetR183_2: Vienna_PFC_EMIFilter (SW2.2), Vienna_PFC_Relay (R183.2)
V_BUS_M: Vienna_PFC_Overall (P4.1), Vienna_PFC_PowerStage (27 pins), Vienna_PFC_OutputVoltageSensor (14 pins), Vienna_PFC_EMIFilter (p8.1 p9.1 p10.1 R4.2)
V_N_Meas: Vienna_PFC_InputVoltageSensor (19 pins), Vienna_PFC_EMIFilter (C14.1 C15.1 C16.1)
VBUSN: Vienna_PFC_Overall (P6.1), Vienna_PFC_PowerStage (14 pins), Vienna_PFC_OutputVoltageSensor (R120.2)
VBUSP: Vienna_PFC_Overall (P2.1), Vienna_PFC_PowerStage (14 pins), Vienna_PFC_OutputVoltageSensor (R108.2)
